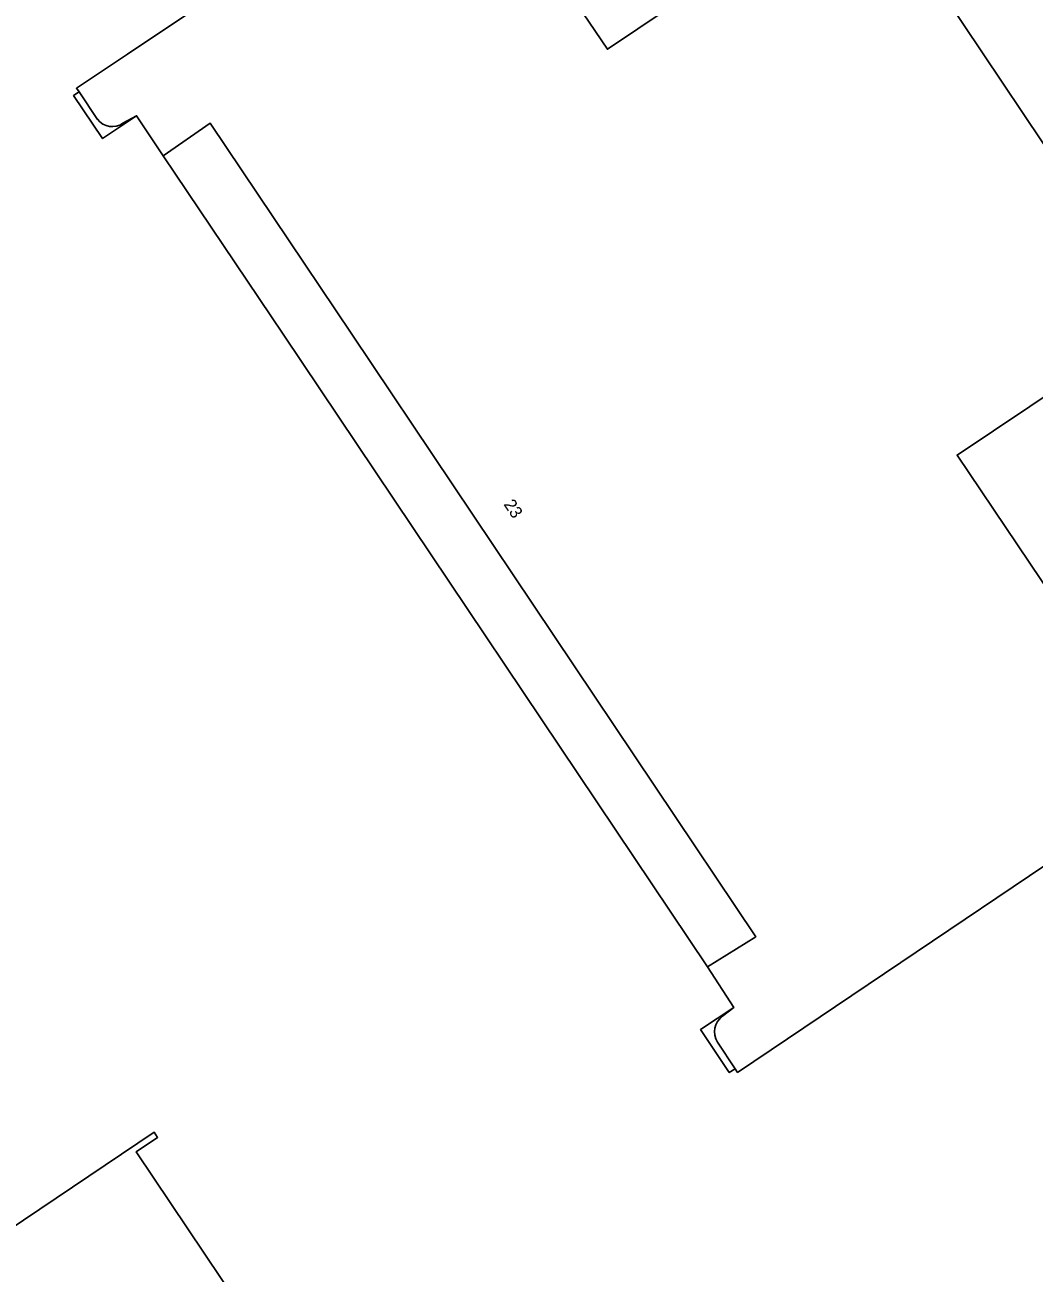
# Model space of a CAD drawing. Extents: x 156702 to 158052, y 387630 to 388992.
# Drawn here: x 157437.9 to 157520.1, y 387923.6 to 388025.2 of the extents above; entities that cross this region are included whole.
import ezdxf

# ---------------------------------------------------------------- set-up
doc = ezdxf.new("R2010")
doc.units = 0
for name, color, linetype in [('IMGEO_Erf', 7, 'Continuous'), ('IMGEO_Pand', 7, 'Continuous'), ('IMGEO_Pand_nummerreeks', 7, 'Continuous'), ('IMGEO_Pand_overbouw', 7, 'Continuous')]:
    doc.layers.add(name, color=color, linetype=linetype)

msp = doc.modelspace()

# ---------------------------------------------------------------- linework, layer by layer
at = {"layer": 'IMGEO_Erf'}
for points in [[(157443.82, 388017.48), (157442.32, 388019.71), (157442.11, 388020.01), (157446.27, 388022.79), (157473.35, 388040.88), (157485.34, 388023.18), (157500, 388033.03), (157506.27, 388037.24), (157530.4, 388001.25), (157528.53, 388000), (157513.82, 387990.16), (157531.52, 387963.86), (157500, 387942.64), (157495.94, 387939.91), (157495.74, 387940.21), (157494.3, 387942.39)], [(157453.01, 388017.17), (157449.18, 388014.51), (157447, 388017.78), (157445.88, 388017.17)], [(157494.72, 387944.48), (157495.65, 387945.21), (157493.49, 387948.51), (157497.43, 387950.95), (157464.53, 388000), (157453.01, 388017.17)], [(157428.45, 387921.62), (157448.45, 387935.04), (157448.72, 387934.63), (157446.96, 387933.45), (157472.05, 387896.09)]]:
    msp.add_lwpolyline(points, dxfattribs=at)
for centre, radius, start, end in [((157445.02, 388018.4), 1.51, 217.3813, 305.0847), ((157495.63, 387943.21), 1.56, 125.3426, 211.7747)]:
    msp.add_arc(centre, radius, start, end, dxfattribs=at)
at = {"layer": 'IMGEO_Pand'}
for points in [[(157494.3, 387942.39), (157495.74, 387940.21), (157495.94, 387939.91), (157500, 387942.64), (157531.52, 387963.86), (157513.82, 387990.16), (157528.53, 388000), (157530.4, 388001.25), (157506.27, 388037.24), (157500, 388033.03), (157485.34, 388023.18), (157473.35, 388040.88), (157446.27, 388022.79), (157442.11, 388020.01), (157442.32, 388019.71), (157443.82, 388017.48)], [(157445.88, 388017.17), (157447, 388017.78), (157449.18, 388014.51), (157453.01, 388017.17), (157464.53, 388000), (157497.43, 387950.95), (157493.49, 387948.51), (157495.65, 387945.21), (157494.72, 387944.48)], [(157472.05, 387896.09), (157446.96, 387933.45), (157448.72, 387934.63), (157448.45, 387935.04), (157428.45, 387921.62)]]:
    msp.add_lwpolyline(points, dxfattribs=at)
for centre, radius, start, end in [((157445.02, 388018.4), 1.51, 217.3813, 305.0847), ((157495.63, 387943.21), 1.56, 125.3426, 211.7747)]:
    msp.add_arc(centre, radius, start, end, dxfattribs=at)
at = {"layer": 'IMGEO_Pand_overbouw'}
for points in [[(157443.82, 388017.48), (157442.32, 388019.71), (157441.88, 388019.41), (157444.23, 388015.91), (157447, 388017.78)], [(157447, 388017.78), (157445.88, 388017.17)], [(157494.72, 387944.48), (157495.65, 387945.21), (157492.93, 387943.4), (157495.27, 387939.9), (157495.74, 387940.21)], [(157495.74, 387940.21), (157494.3, 387942.39)]]:
    msp.add_lwpolyline(points, dxfattribs=at)
msp.add_lwpolyline([(157493.49, 387948.51), (157497.43, 387950.95), (157464.53, 388000), (157453.01, 388017.17), (157449.18, 388014.51), (157458.95, 388000)], close=True, dxfattribs=at)
for centre, radius, start, end in [((157445.02, 388018.4), 1.51, 217.3813, 305.0847), ((157495.63, 387943.21), 1.56, 125.3426, 211.7747)]:
    msp.add_arc(centre, radius, start, end, dxfattribs=at)

# ---------------------------------------------------------------- texts
at = {"layer": 'IMGEO_Pand_nummerreeks'}
msp.add_text('23', height=1, rotation=303.8535, dxfattribs=at).set_placement((157476.86, 387986.15))

doc.saveas('drawing.dxf')
